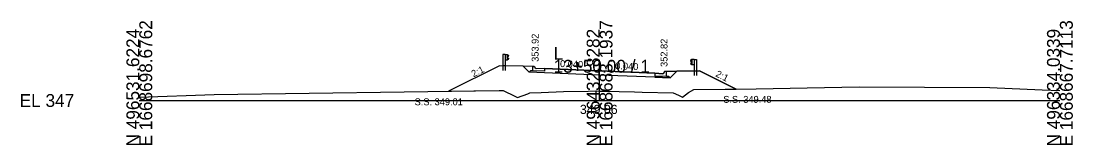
# Model space of a CAD drawing. Extents: x -26 to 203, y -10 to 5517.
# Drawn here: x -25.7 to 202.8, y 3490.3 to 3517.3 of the extents above; entities that cross this region are included whole.
import ezdxf

# ---------------------------------------------------------------- set-up
doc = ezdxf.new("R2010")
doc.units = 0
for name, color, linetype in [('Exist Cross Section Cell', 7, 'Continuous'), ('Exist XS Center Line Elevation Label', 7, 'Continuous'), ('Exist XS Ground Line', 7, 'Continuous'), ('Prop XS Earthwork Shape', 7, 'Continuous'), ('Prop XS Finish Grade', 7, 'Continuous'), ('Prop XS Finish Grade CurbGutter', 7, 'Continuous'), ('Prop XS Finish Grade Earthwork', 7, 'Continuous'), ('Prop XS Finish Grade Pavement', 7, 'Continuous'), ('Prop XS Geopak Shape', 7, 'Continuous'), ('Prop XS Hydro Elevations', 7, 'Continuous'), ('Prop XS Pvmt Edge Slope', 7, 'Continuous'), ('Prop XS SE Text', 7, 'Continuous'), ('Prop XS Side Slope Text', 7, 'Continuous'), ('Prop XS SS Elevation Text', 7, 'Continuous'), ('Prop XS Subgrade CurbGutter', 7, 'Continuous'), ('Prop XS Subgrade Earthwork', 7, 'Continuous'), ('Typical Guardrail CELL', 7, 'Continuous')]:
    doc.layers.add(name, color=color, linetype=linetype)

msp = doc.modelspace()

# ---------------------------------------------------------------- linework, layer by layer
at = {"layer": 'Exist Cross Section Cell'}
for p, q in [((100, 3500), (100, 3508.86)), ((0, 3500), (100, 3500)), ((100, 3500), (200, 3500))]:
    msp.add_line(p, q, dxfattribs=at)
at = {"layer": 'Exist XS Ground Line'}
for p, q in [((0, 3500.7), (16.29, 3501.34)), ((16.29, 3501.34), (78.19, 3502.15)), ((78.19, 3502.15), (79.06, 3502.19)), ((79.06, 3502.19), (81.55, 3500.94)), ((82.2, 3500.64), (84.4, 3501.48)), ((84.4, 3501.48), (84.85, 3501.65)), ((84.85, 3501.65), (87.31, 3501.73)), ((87.31, 3501.73), (92.19, 3501.96)), ((92.19, 3501.96), (97.49, 3502.06)), ((97.49, 3502.06), (99.11, 3502.09)), ((99.11, 3502.09), (100, 3502.06)), ((100, 3502.06), (100.95, 3502.03)), ((100.95, 3502.03), (107.58, 3501.9)), ((107.58, 3501.9), (109.28, 3501.82)), ((109.28, 3501.82), (115.95, 3501.65)), ((115.95, 3501.65), (117.12, 3501.13)), ((117.12, 3501.13), (117.99, 3500.75)), ((117.99, 3500.75), (119.35, 3501.74)), ((119.35, 3501.74), (120.48, 3502.42)), ((120.48, 3502.42), (133.99, 3502.51)), ((133.99, 3502.51), (145.12, 3502.79)), ((145.12, 3502.79), (156.38, 3502.95)), ((156.38, 3502.95), (184.77, 3502.81)), ((184.77, 3502.81), (196.12, 3502.33)), ((196.12, 3502.33), (200, 3502.2)), ((81.55, 3500.94), (82.2, 3500.64))]:
    msp.add_line(p, q, dxfattribs=at)
at = {"layer": 'Prop XS Earthwork Shape'}
msp.add_lwpolyline([(112, 3505.06), (100, 3505.54), (88, 3506.02), (84.67, 3506.16), (83.36, 3507.46), (78.27, 3507.57), (67.15, 3502.01), (78.19, 3502.15), (79.06, 3502.19), (81.55, 3500.94), (82.2, 3500.64), (84.4, 3501.48), (84.85, 3501.65), (87.31, 3501.73), (92.19, 3501.96), (97.49, 3502.06), (99.11, 3502.09), (100, 3502.06), (100.95, 3502.03), (107.58, 3501.9), (109.28, 3501.82), (115.95, 3501.65), (117.12, 3501.13), (117.99, 3500.75), (119.35, 3501.74), (120.48, 3502.42), (129.7, 3502.48), (121.73, 3506.47), (116.77, 3506.36), (115.33, 3504.93)], close=True, dxfattribs=at)
at = {"layer": 'Prop XS Finish Grade'}
for p, q in [((85.5, 3507.42), (83.36, 3507.46)), ((114.5, 3506.32), (116.77, 3506.36))]:
    msp.add_line(p, q, dxfattribs=at)
at = {"layer": 'Prop XS Finish Grade CurbGutter'}
for p, q in [((85.5, 3507.42), (85.75, 3507.42)), ((85.75, 3507.42), (85.88, 3507.37)), ((85.97, 3507.28), (85.88, 3507.37)), ((86.03, 3507.03), (85.97, 3507.28)), ((86.13, 3506.94), (86.03, 3507.03)), ((86.25, 3506.92), (86.13, 3506.94)), ((88, 3506.94), (86.25, 3506.92)), ((112, 3505.98), (113.75, 3505.84)), ((113.75, 3505.84), (113.87, 3505.86)), ((113.87, 3505.86), (113.97, 3505.95)), ((113.97, 3505.95), (114.03, 3506.2)), ((114.03, 3506.2), (114.12, 3506.29)), ((114.25, 3506.32), (114.12, 3506.29)), ((114.5, 3506.32), (114.25, 3506.32))]:
    msp.add_line(p, q, dxfattribs=at)
at = {"layer": 'Prop XS Finish Grade Earthwork'}
for p, q in [((78.27, 3507.57), (67.15, 3502.01)), ((83.36, 3507.46), (78.27, 3507.57)), ((116.77, 3506.36), (121.73, 3506.47)), ((121.73, 3506.47), (129.7, 3502.48))]:
    msp.add_line(p, q, dxfattribs=at)
at = {"layer": 'Prop XS Finish Grade Pavement'}
for p, q in [((88, 3506.94), (100, 3506.46)), ((100, 3506.46), (112, 3505.98))]:
    msp.add_line(p, q, dxfattribs=at)
at = {"layer": 'Prop XS Geopak Shape'}
msp.add_lwpolyline([(85.5, 3507.42), (83.36, 3507.46), (78.27, 3507.57), (67.15, 3502.01), (78.19, 3502.15), (79.06, 3502.19), (81.55, 3500.94), (82.2, 3500.64), (84.4, 3501.48), (84.85, 3501.65), (87.31, 3501.73), (92.19, 3501.96), (97.49, 3502.06), (99.11, 3502.09), (100, 3502.06), (100.95, 3502.03), (107.58, 3501.9), (109.28, 3501.82), (115.95, 3501.65), (117.12, 3501.13), (117.99, 3500.75), (119.35, 3501.74), (120.48, 3502.42), (129.7, 3502.48), (121.73, 3506.47), (116.77, 3506.36), (114.5, 3506.32), (114.25, 3506.32), (114.12, 3506.29), (114.03, 3506.2), (113.97, 3505.95), (113.87, 3505.86), (113.75, 3505.84), (112, 3505.98), (100, 3506.46), (88, 3506.94), (86.25, 3506.92), (86.13, 3506.94), (86.03, 3507.03), (85.97, 3507.28), (85.88, 3507.37), (85.75, 3507.42)], close=True, dxfattribs=at)
at = {"layer": 'Prop XS Pvmt Edge Slope'}
for p, q in [((85, 3506.48), (84.67, 3506.16)), ((85.5, 3506.46), (85, 3506.48)), ((114.5, 3505.3), (115, 3505.28)), ((115, 3505.28), (115.33, 3504.93))]:
    msp.add_line(p, q, dxfattribs=at)
at = {"layer": 'Prop XS Subgrade CurbGutter'}
for p, q in [((85.5, 3506.46), (85.5, 3507.42)), ((88, 3506.36), (85.5, 3506.46)), ((88, 3506.94), (88, 3506.36)), ((112, 3505.98), (112, 3505.4)), ((114.5, 3505.3), (114.5, 3506.32)), ((112, 3505.4), (114.5, 3505.3))]:
    msp.add_line(p, q, dxfattribs=at)
at = {"layer": 'Prop XS Subgrade Earthwork'}
for p, q in [((84.67, 3506.16), (83.36, 3507.46)), ((88, 3506.02), (84.67, 3506.16)), ((88, 3506.02), (88, 3506.02)), ((100, 3505.54), (88, 3506.02)), ((115.33, 3504.93), (116.77, 3506.36)), ((112, 3505.06), (100, 3505.54)), ((112, 3505.06), (112, 3505.06)), ((112, 3505.06), (115.33, 3504.93))]:
    msp.add_line(p, q, dxfattribs=at)
at = {"layer": 'Typical Guardrail CELL'}
for p, q in [((79.45, 3510.03), (78.95, 3510.03)), ((78.95, 3510.03), (78.95, 3507.54)), ((79.45, 3510.03), (79.45, 3507.54)), ((79.45, 3510.03), (79.95, 3510.03)), ((79.45, 3508.87), (79.95, 3508.87)), ((79.95, 3510.03), (79.95, 3508.87)), ((79.95, 3510.03), (80.24, 3509.83)), ((79.95, 3509.5), (80.24, 3509.7)), ((79.95, 3509.45), (79.95, 3509.5)), ((79.95, 3509.45), (79.95, 3509.4)), ((79.95, 3509.4), (80.24, 3509.2)), ((79.95, 3508.87), (80.24, 3509.07)), ((120.05, 3508.93), (119.76, 3508.73)), ((120.05, 3508.4), (119.76, 3508.6)), ((120.05, 3508.3), (119.76, 3508.1)), ((120.55, 3508.93), (120.05, 3508.93)), ((120.05, 3508.93), (120.05, 3507.77)), ((120.05, 3508.35), (120.05, 3508.4)), ((120.05, 3508.35), (120.05, 3508.3)), ((120.55, 3508.93), (120.55, 3506.44)), ((120.55, 3508.93), (121.05, 3508.93)), ((121.05, 3508.93), (121.05, 3506.44)), ((79.45, 3507.54), (78.95, 3507.54)), ((78.95, 3507.54), (78.95, 3506.54)), ((79.45, 3507.54), (79.45, 3506.54)), ((120.05, 3507.77), (119.76, 3507.97)), ((120.55, 3507.77), (120.05, 3507.77)), ((120.55, 3506.44), (121.05, 3506.44)), ((120.55, 3506.44), (120.55, 3505.43)), ((121.05, 3506.44), (121.05, 3505.43))]:
    msp.add_line(p, q, dxfattribs=at)
for centre, start, end in [((80.19, 3509.76), 304.9888, 54.997), ((80.19, 3509.14), 304.9634, 54.9941), ((119.81, 3508.66), 125.003, 235.0112), ((119.81, 3508.03), 125.0059, 235.0366)]:
    msp.add_arc(centre, 0.0776, start, end, dxfattribs=at)

# ---------------------------------------------------------------- texts
at = {"layer": 'Exist Cross Section Cell'}
for s, p in [('E 1668698.6762', (2.8, 3490)), ('E 1668683.1937', (102.8, 3490)), ('E 1668667.7113', (202.8, 3490)), ('N 496531.6224', (0, 3490)), ('N 496432.8282', (100, 3490)), ('N 496334.0339', (200, 3490))]:
    msp.add_text(s, height=2.8, rotation=90, dxfattribs=at).set_placement(p)
for s, p in [('L', (90, 3508.86)), ('13+50.00 / 1', (90, 3506.06)), ('EL 347', (-26, 3498.6))]:
    msp.add_text(s, height=2.8, dxfattribs=at).set_placement(p)
at = {"layer": 'Exist XS Center Line Elevation Label'}
msp.add_text('349.06', height=2, dxfattribs=at).set_placement((95.73, 3497.06))
at = {"layer": 'Prop XS Hydro Elevations'}
for s, p in [('353.92', (86.75, 3508.42)), ('352.82', (114.75, 3507.32))]:
    msp.add_text(s, height=1.5, rotation=90, dxfattribs=at).set_placement(p)
at = {"layer": 'Prop XS SE Text'}
for p in [(91.38, 3507.3), (103.38, 3506.82)]:
    msp.add_text('0.040', height=1.5, rotation=357.7094, dxfattribs=at).set_placement(p)
at = {"layer": 'Prop XS Side Slope Text'}
for rotation, p in [(26.5651, (72.6, 3505.02)), (333.4349, (125.05, 3505.3))]:
    msp.add_text('2:1', height=1.5, rotation=rotation, dxfattribs=at).set_placement(p)
at = {"layer": 'Prop XS SS Elevation Text'}
for s, p in [('S.S. 349.01', (59.81, 3498.97)), ('S.S. 349.48', (126.87, 3499.5))]:
    msp.add_text(s, height=1.5, dxfattribs=at).set_placement(p)

doc.saveas('drawing.dxf')
